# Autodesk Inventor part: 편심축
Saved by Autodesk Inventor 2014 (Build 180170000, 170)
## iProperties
Created: 2026-03
Part Number: 편심축
Material: 일반
Document SubType Name: Modeling
Designer: dg
Density: 1 g/cm^3
Appearance: 기본값
Author: dg
Author: jhkim
Creation Date: 2025-06-27
Sending System: Autodesk Inventor 2026
Preprocessor: ST-DEVELOPER v20.1
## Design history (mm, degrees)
node "편심축1"
node "솔리드1"
node "기준1"
